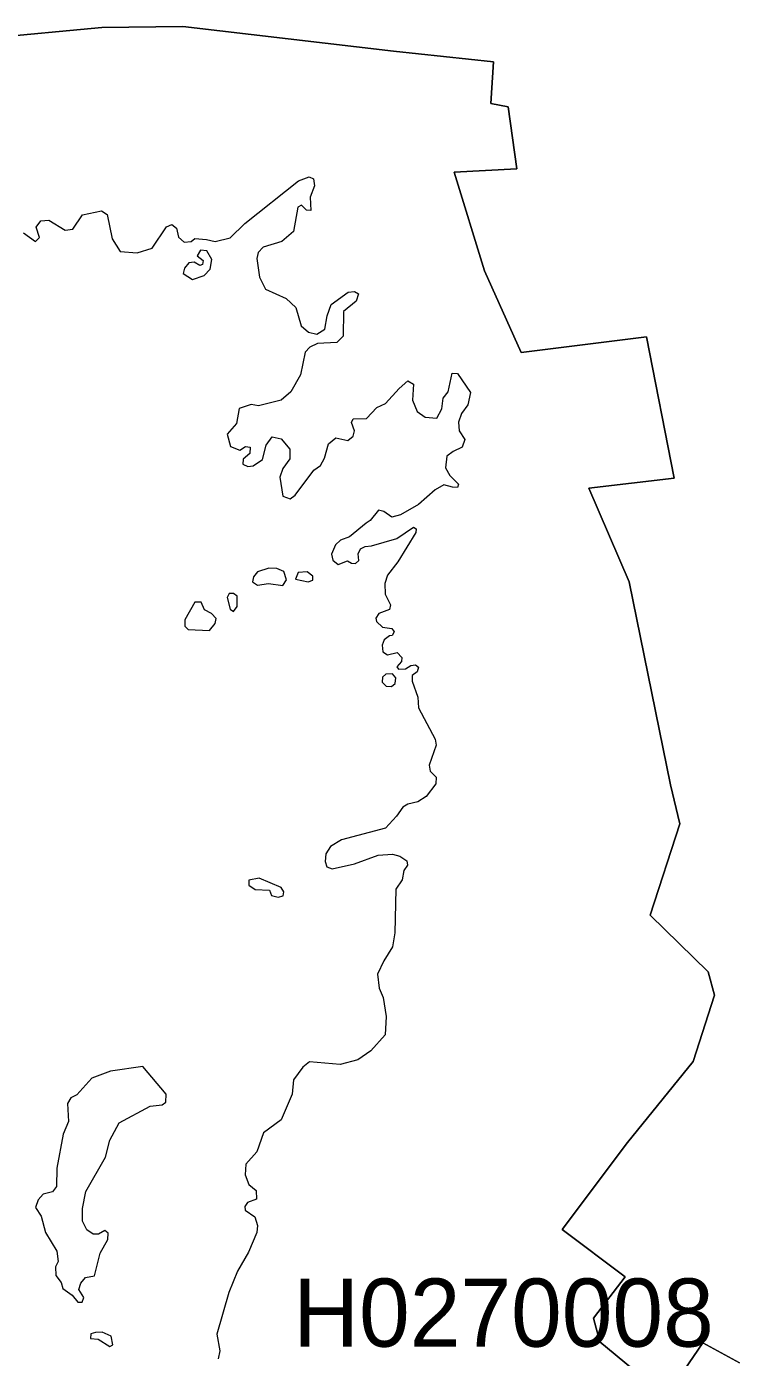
# Model space of a CAD drawing. Extents: x 369010 to 739155, y 6377141 to 6616555.
# Drawn here: x 414085 to 415131, y 6456234 to 6458187 of the extents above; entities that cross this region are included whole.
import ezdxf
from ezdxf.enums import TextEntityAlignment as Align

# ---------------------------------------------------------------- set-up
doc = ezdxf.new("R2010")
doc.units = 0
doc.header["$LTSCALE"] = 40
doc.layers.add('1', color=7, linetype='Continuous', lineweight=13)
doc.layers.add('2', color=7, linetype='Continuous')

msp = doc.modelspace()

# ---------------------------------------------------------------- linework, layer by layer
at = {"layer": '1'}
for points in [[(414028.29, 6458169.76), (414195.45, 6458185.32), (414314.28, 6458186.64), (414623.77, 6458150.56), (414770.24, 6458135), (414766.43, 6458073.93), (414792.09, 6458069.13), (414804.83, 6457977.94), (414712.81, 6457973.14), (414757.33, 6457828.32), (414811.12, 6457708.5), (414995.16, 6457731.5), (415035.71, 6457523.96), (414910.26, 6457509.23), (414969.51, 6457372.03), (415030.41, 6457074.29), (415043.98, 6457017.02), (415000.62, 6456882.97), (415085.53, 6456799.88), (415094.79, 6456765.29), (415063.35, 6456668.31), (414967.19, 6456549.48), (414871.2, 6456421.37), (414963.55, 6456352.03), (414917.37, 6456291.45), (414926.64, 6456256.86), (414974.47, 6456217.14)], [(414974.47, 6456217.14), (414926.64, 6456256.86), (414917.37, 6456291.45), (414963.55, 6456352.03), (414871.2, 6456421.37), (414967.19, 6456549.48), (415063.35, 6456668.31), (415094.79, 6456765.29), (415085.53, 6456799.88), (415000.62, 6456882.97), (415043.98, 6457017.02), (415030.41, 6457074.29), (414969.51, 6457372.03), (414910.26, 6457509.23), (415035.71, 6457523.96), (414995.16, 6457731.5), (414811.12, 6457708.5), (414757.33, 6457828.32), (414712.81, 6457973.14), (414804.83, 6457977.94), (414792.09, 6458069.13), (414766.43, 6458073.93), (414770.24, 6458135), (414623.77, 6458150.56), (414314.28, 6458186.64), (414195.45, 6458185.32), (414028.29, 6458169.76)], [(414326.69, 6457871.52), (414331.99, 6457875.66), (414349.03, 6457874.5), (414362.11, 6457871.52), (414383.95, 6457876.65), (414405.3, 6457897.51), (414484.08, 6457960.4), (414499.81, 6457966.19), (414506.1, 6457963.04), (414507.92, 6457953.11), (414501.63, 6457936.4), (414502.46, 6457917.03), (414496.17, 6457917.53), (414488.55, 6457924.65), (414483.09, 6457921.5), (414476.8, 6457885.92), (414459.76, 6457871.52), (414432.61, 6457862.91), (414425, 6457855.3), (414423.18, 6457846.2), (414427.15, 6457819.22), (414435.76, 6457801.18), (414466.04, 6457787.61), (414480.44, 6457774.54), (414488.06, 6457747.56), (414498.98, 6457738.46), (414511.06, 6457735.31), (414522.81, 6457742.92), (414526.45, 6457762.29), (414532.25, 6457778.67), (414557.07, 6457797.04), (414566.51, 6457798.04), (414572.46, 6457794.4), (414568.82, 6457783.97), (414550.29, 6457768.74), (414549.96, 6457732.66), (414540.36, 6457723.06), (414512.06, 6457721.74), (414501.13, 6457716.28), (414494.02, 6457709.16), (414487.23, 6457675.73), (414472.83, 6457650.9), (414458.76, 6457638.33), (414425.66, 6457630.22), (414414.9, 6457632.04), (414397.2, 6457626.08), (414393.22, 6457604.07), (414379.65, 6457588.67), (414384.62, 6457570.63), (414398.19, 6457565.34), (414406.63, 6457570.63), (414413.41, 6457569.31), (414413.08, 6457560.37), (414403.15, 6457551.77), (414402.66, 6457544.49), (414409.94, 6457541.34), (414417.55, 6457542.33), (414431.45, 6457551.27), (414436.92, 6457572.46), (414445.52, 6457584.7), (414458.6, 6457581.89), (414471.67, 6457566.66), (414471.67, 6457552.26), (414461.25, 6457538.2), (414456.78, 6457525.62), (414461.25, 6457497.65), (414472.17, 6457493.51), (414479.29, 6457498.97), (414506.76, 6457535.88), (414516.36, 6457542.66), (414522.65, 6457553.59), (414528.44, 6457574.28), (414539.03, 6457583.38), (414556.58, 6457579.24), (414564.35, 6457585.53), (414566.51, 6457593.64), (414562.04, 6457605.89), (414564.69, 6457611.35), (414584.21, 6457611.68), (414599.11, 6457627.9), (414612.18, 6457633.86), (414631.88, 6457655.87), (414644.95, 6457666.79), (414653.06, 6457662.16), (414651.41, 6457638.33), (414658.53, 6457622.11), (414670.28, 6457613.5), (414687.16, 6457612.18), (414694.77, 6457625.75), (414696.59, 6457641.47), (414703.87, 6457650.9), (414709.67, 6457678.05), (414717.45, 6457677.55), (414736.81, 6457649.58), (414732.67, 6457631.54), (414723.73, 6457618.96), (414719.27, 6457606.38), (414720.09, 6457593.31), (414728.2, 6457580.56), (414724.56, 6457569.31)], [(414080.59, 6457883.93), (414098.3, 6457871.52), (414103.92, 6457877.15), (414099.29, 6457892.21), (414106.07, 6457901.64), (414117.99, 6457902.64), (414141.99, 6457888.07), (414152.91, 6457889.23), (414167.48, 6457910.41), (414195.11, 6457916.21), (414203.39, 6457911.08), (414210.67, 6457875.16), (414222.59, 6457856.79), (414247.58, 6457854.81), (414269.43, 6457861.59), (414290.78, 6457892.87), (414298.55, 6457896.51), (414305.34, 6457890.72), (414307.99, 6457877.64), (414316.26, 6457870.36), (414326.69, 6457871.52)], [(414724.56, 6457569.31), (414711.49, 6457563.02), (414702.05, 6457556.24), (414700.23, 6457539.19), (414706.19, 6457527.77), (414719.27, 6457515.19), (414717.78, 6457510.23), (414710.16, 6457510.72), (414697.59, 6457514.36), (414685.01, 6457507.08), (414660.51, 6457485.4), (414634.2, 6457470.17), (414621.45, 6457466.7), (414609.37, 6457475.3), (414601.92, 6457477.29), (414589.35, 6457461.73), (414583.39, 6457458.09), (414559.22, 6457437.9), (414545.98, 6457432.94), (414538.37, 6457426.15), (414532.58, 6457412.58), (414534.56, 6457403.97), (414542.51, 6457397.19), (414556.08, 6457402.81), (414561.87, 6457399.34), (414568.16, 6457399.01), (414572.8, 6457403.48), (414571.97, 6457413.07), (414575.44, 6457420.52), (414582.23, 6457423.67), (414591.33, 6457424.66), (414628.74, 6457435.58), (414652.9, 6457451.97), (414657.2, 6457449.65), (414656.37, 6457444.36), (414629.89, 6457401.32), (414614.67, 6457381.63), (414610.86, 6457369.38), (414611.52, 6457353.66), (414619.47, 6457338.43), (414617.98, 6457331.32), (414602.42, 6457325.69), (414597.95, 6457318.41), (414598.61, 6457313.94), (414607.39, 6457305.5), (414621.29, 6457303.35), (414624.76, 6457298.38), (414621.78, 6457293.42), (414617.98, 6457292.75), (414610.03, 6457286.63), (414607.05, 6457279.02), (414608.21, 6457269.25), (414615, 6457264.62), (414628.9, 6457268.42), (414635.85, 6457260.98), (414635.36, 6457254.85), (414628.57, 6457247.24), (414631.22, 6457243.93), (414641.15, 6457244.26), (414649.09, 6457249.23), (414656.21, 6457250.22), (414660.35, 6457246.91), (414658.53, 6457240.12), (414651.24, 6457234.33), (414650.91, 6457226.06), (414659.52, 6457202.55), (414660.35, 6457186.83), (414685.01, 6457141.32), (414686.5, 6457132.38), (414675.9, 6457102.75), (414677.72, 6457093.98), (414686.5, 6457085.38), (414685.67, 6457075.61), (414671.77, 6457057.08), (414659.52, 6457049.13), (414644.79, 6457045.66), (414637.18, 6457041.52), (414627.91, 6457028.28), (414611.85, 6457010.4), (414547.31, 6456993.52), (414531.42, 6456983.59), (414524.47, 6456973), (414523.31, 6456961.58), (414525.96, 6456953.8), (414533.9, 6456950.66), (414566.34, 6456957.94), (414601.43, 6456970.85), (414622.28, 6456972.17), (414632.87, 6456969.52), (414643.13, 6456962.41), (414644.29, 6456955.95), (414638.67, 6456948.34), (414636.35, 6456934.77), (414627.25, 6456920.87), (414625.43, 6456856.98), (414622.28, 6456836.13), (414609.54, 6456815.61), (414600.1, 6456796.41), (414602.59, 6456775.55), (414608.71, 6456761.98)], [(414608.71, 6456761.98), (414612.85, 6456734.34), (414611.69, 6456707.37), (414590.5, 6456683.7), (414571.31, 6456670.79), (414545.49, 6456663.51), (414500.47, 6456667.81), (414490.71, 6456659.87), (414477.13, 6456641.33), (414475.15, 6456620.15), (414458.93, 6456582.58), (414432.78, 6456563.38), (414423.34, 6456535.41), (414407.13, 6456517.53), (414405.8, 6456501.64), (414411.26, 6456487.58), (414422.19, 6456478.97), (414422.52, 6456466.06), (414409.61, 6456461.1), (414405.47, 6456455.14), (414405.8, 6456450.17), (414420.2, 6456440.08), (414424.01, 6456427.5), (414423.01, 6456417.24), (414410.77, 6456388.27), (414394.55, 6456360.63), (414381.97, 6456329.19), (414364.26, 6456267.95), (414368.73, 6456243.62), (414366.25, 6456231.87)], [(415050.27, 6456215.32), (415077.91, 6456255.21), (415131.37, 6456225.75)], [(415131.37, 6456225.75), (415077.91, 6456255.21), (415050.27, 6456215.32)]]:
    msp.add_lwpolyline(points, dxfattribs=at)
for points in [[(414340.43, 6457858.45), (414335.46, 6457850.34), (414344.4, 6457843.55), (414343.57, 6457837.76), (414339.6, 6457836.27), (414330.99, 6457841.23), (414323.22, 6457839.91), (414316.93, 6457832.3), (414315.11, 6457824.19), (414328.68, 6457815.58), (414345.89, 6457821.37), (414354.83, 6457830.97), (414357.14, 6457844.87), (414349.86, 6457857.45)], [(414461.41, 6457366.73), (414466.87, 6457374.84), (414462.73, 6457387.26), (414452.47, 6457391.72), (414440.72, 6457392.22), (414424.34, 6457386.43), (414418.38, 6457379.31), (414416.89, 6457372.03), (414424.34, 6457366.9), (414440.23, 6457369.55)], [(414498.32, 6457372.03), (414505.1, 6457374.35), (414505.1, 6457380.47), (414496.99, 6457386.43), (414483.92, 6457385.44), (414479.78, 6457376)], [(414353.5, 6457300.7), (414362.11, 6457310.79), (414363.27, 6457318.08), (414356.48, 6457325.69), (414346.22, 6457330.98), (414341.42, 6457341.91), (414331.99, 6457341.91), (414317.26, 6457316.09), (414317.26, 6457306.66), (414322.39, 6457301.86)], [(414388.75, 6457354.82), (414382.63, 6457354.82), (414379.65, 6457349.02), (414384.12, 6457331.98), (414388.75, 6457328.17), (414394.38, 6457335.78), (414394.05, 6457351.01)], [(414620.63, 6457218.44), (414625.92, 6457222.75), (414627.08, 6457231.02), (414622.12, 6457236.98), (414612.68, 6457236.65), (414607.72, 6457231.85), (414607.05, 6457224.57), (414613.01, 6457218.61)], [(414454.29, 6456909.28), (414461.58, 6456911.1), (414462.73, 6456917.06), (414458.93, 6456923.18), (414426.32, 6456937.25), (414411.26, 6456934.11), (414411.26, 6456926.66), (414420.7, 6456920.53), (414441.88, 6456919.54), (414444.86, 6456911.6)], [(414255.69, 6456660.53), (414208.36, 6456653.74), (414180.72, 6456643.48), (414158.7, 6456618.99), (414149.93, 6456614.85), (414145.3, 6456606.57), (414146.79, 6456580.09), (414139.01, 6456561.56), (414129.58, 6456511.57), (414128.91, 6456484.6), (414123.29, 6456476.82), (414109.71, 6456473.67), (414102.43, 6456465.07), (414098.3, 6456453.98), (414106.57, 6456441.07), (414112.86, 6456417.4), (414129.41, 6456389.76), (414131.73, 6456374.87), (414127.59, 6456366.92), (414128.25, 6456353.85), (414136.03, 6456343.59), (414138.51, 6456334.82), (414152.25, 6456325.38), (414160.52, 6456315.12), (414166.98, 6456314.79), (414169.13, 6456321.91), (414161.68, 6456333.33), (414164.66, 6456342.76), (414171.78, 6456351.04), (414184.85, 6456353.68), (414193.29, 6456386.78), (414204.22, 6456407.14), (414205.05, 6456416.24), (414200.08, 6456419.89), (414190.65, 6456414.59), (414182.7, 6456414.75), (414173.6, 6456421.04), (414167.48, 6456433.62), (414167.14, 6456452.16), (414171.94, 6456477.15), (414200.91, 6456527.79), (414207.53, 6456552.45), (414220.93, 6456578.11), (414266.61, 6456602.77), (414284.16, 6456604.59), (414289.78, 6456608.39), (414290.11, 6456619.98)], [(414207.36, 6456249.75), (414212, 6456252.4), (414209.35, 6456265.14), (414196.11, 6456270.93), (414186.34, 6456270.6), (414179.72, 6456268.61), (414179.06, 6456261.5), (414190.32, 6456260.67)]]:
    msp.add_lwpolyline(points, close=True, dxfattribs=at)

# ---------------------------------------------------------------- texts
at = {"layer": '2'}
msp.add_text('H0270008', height=100, dxfattribs=at).set_placement((414785.2, 6456249.66), align=Align.CENTER)

doc.saveas('drawing.dxf')
